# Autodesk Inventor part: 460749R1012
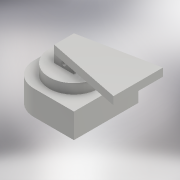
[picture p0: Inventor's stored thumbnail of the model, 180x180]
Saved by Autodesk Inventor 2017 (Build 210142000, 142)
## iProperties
Created: 2016-07
Part Number: 460749R1012
Material: Aluminum 6061
Document SubType Name: Modeling
Designer: Polytech
Mass: 1260.26 g
Surface Area: 611.154 cm^2
Volume: 466.762 cm^3
Density: 2.7 g/cm^3
Appearance: Aluminum - Flat
Author: Polytech
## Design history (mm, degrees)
sketch "Sketch1"
  geometry: C1 r 23 at (0, 0); 1 further point
  constraints: 1 centre point, 1 coincident
  dimensions: "d0" = 46 diameter of C1
extrude "Extrusion1" new body sketch "Sketch1" distance "d1" = 18; taper "d2" = 0 deg
sketch "Sketch2"
  geometry: L1 (48.75, -48.75)-(-11.75, -48.75); L2 (-48.75, -11.75)-(-48.75, 11.75); L3 (-11.75, 48.75)-(48.75, 48.75); L4 (48.75, 48.75)-(48.75, -48.75); L5 (48.75, -48.75)-(-48.75, 48.75); L6 (-48.75, -48.75)-(48.75, 48.75); A1 r 37 centre (-11.75, 11.75) between (-11.75, 48.75) and (-48.75, 11.75); A2 r 37 centre (-11.75, -11.75) between (-48.75, -11.75) and (-11.75, -48.75); 1 further point
  constraints: 12 end point, 4 point on circle, 4 point on line, 4 tangent, 2 centre point, 2 midpoint, 2 parallel, 1 equal radius, 1 horizontal, 1 perpendicular
  dimensions: "d3" = 97.5 distance of L5.end L3.end; "d4" = 97.5 distance of L6.start L5.end; "d5" = 37 radius of A1
extrude "Extrusion2" join sketch "Sketch2" distance "d6" = 37.5; taper "d7" = 0 deg
sketch "Sketch3"
  geometry: C1 r 37.5 at (0, 0); 1 further point
  constraints: 1 centre point, 1 coincident
  dimensions: "d8" = 75 diameter of C1
extrude "Extrusion3" join sketch "Sketch3" distance "d9" = 15; taper "d10" = 0 deg
sketch "Sketch4"
  geometry: L1 (15, -15)-(-15, -15); L2 (-15, -15)-(-15, 15); L3 (-15, 15)-(15, 15); L4 (15, 15)-(15, -15); L5 (15, -15)-(-15, 15); L6 (-15, -15)-(15, 15); 1 further point
  constraints: 12 end point, 2 midpoint, 2 parallel, 1 horizontal, 1 perpendicular
  dimensions: "d11" = 30 distance of L2.end L3.end; "d12" = 30 distance of L1.end L2.end
extrude "Extrusion4" join sketch "Sketch4" distance "d13" = 12; taper "d14" = 0 deg
sketch "Sketch5"
  geometry: L1 (15, -6)-(-15, -6); L2 (-15, -6)-(-15, 6); L3 (-15, 6)-(15, 6); L4 (15, 6)-(15, -6); L5 (15, -6)-(-15, 6); L6 (-15, -6)-(15, 6); 1 further point
  constraints: 12 end point, 2 midpoint, 2 parallel, 1 horizontal, 1 perpendicular
  dimensions: "d15" = 30 distance of L2.end L3.end; "d16" = 12 distance of L1.end L2.end
extrude "Extrusion5" cut sketch "Sketch5" distance "d17" = 12; taper "d18" = 0 deg
sketch "Sketch6"
  geometry: L1 (52.5, 0)-(-22.5, 0) reference; C1 r 3 at (15, 6); 1 further point
  constraints: 1 centre point, 1 vertical alignment
  dimensions: "d19" = 3 radius of C1; "d20" = 6 distance from line of L1 C1.centre
extrude "Extrusion6" cut sketch "Sketch6" stored distance "d21" = 12; taper "d22" = 0 deg
sketch "Sketch7"
  geometry: L1 (-15, 15)-(-15, -15); L2 (-15, -15)-(97.5, -37.5); L3 (97.5, -37.5)-(97.5, 37.5); L4 (97.5, 37.5)-(-15, 15); 4 further points
  constraints: 8 end point, 2 coincident, 1 horizontal alignment, 1 midpoint, 1 parallel, 1 vertical
  dimensions: "d23" = 97.5 distance from line of L3 point (0, 0); "d24" = 75 distance of L2.end L3.end
extrude "Extrusion7" join sketch "Sketch7" distance "d25" = 12; taper "d26" = 0 deg
sketch "Sketch8"
  geometry: C1 r 23 at (0, 0); 1 further point
  constraints: 1 centre point, 1 coincident
  dimensions: "d27" = 46 diameter of C1
extrude "Extrusion8" cut sketch "Sketch8" distance "d28" = 24.5; taper "d29" = 0 deg
body "Solid1"
